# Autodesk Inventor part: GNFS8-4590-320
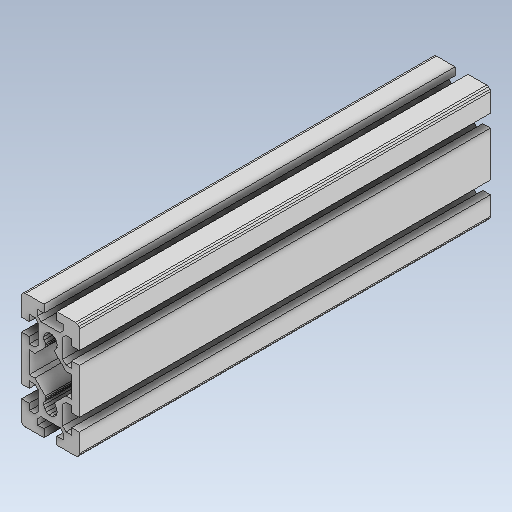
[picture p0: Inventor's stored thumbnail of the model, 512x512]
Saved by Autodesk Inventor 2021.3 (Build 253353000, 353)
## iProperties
Created: 2022-02
Part Number: GNFS8-4590-320
Material: 一般
Document SubType Name: Modeling
Designer: kengo
Density: 1 g/cm^3
Appearance: 既定
Author: kengo
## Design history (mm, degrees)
feature "GNFS8-4590-320"
node "ソリッド1"
